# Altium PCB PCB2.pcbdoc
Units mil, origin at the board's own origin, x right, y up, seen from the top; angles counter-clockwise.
Board outline 3655 x 4282.74 mil, 2 copper layers (Top Layer, Bottom Layer); 22 components, 12 nets, 101 pads, 23 vias.
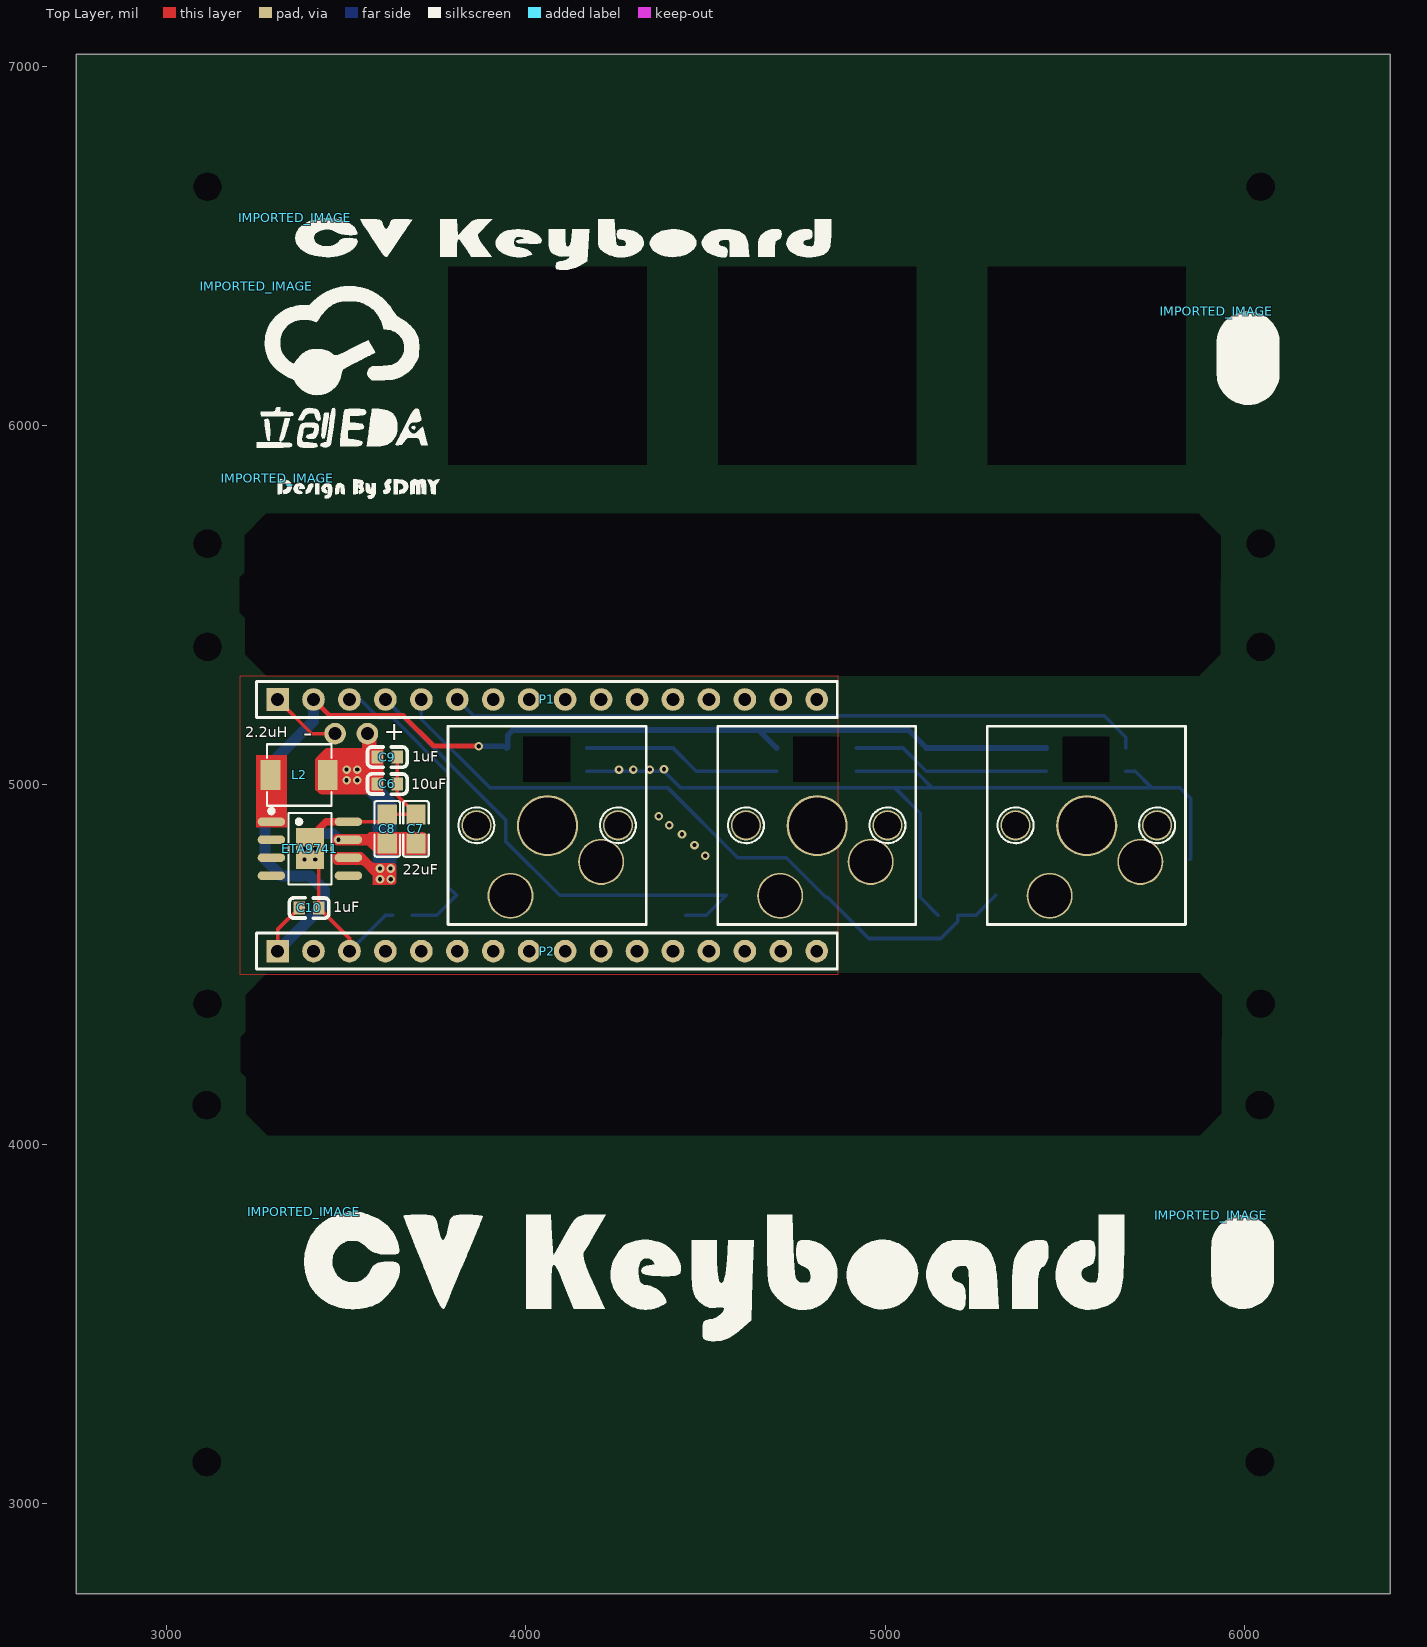
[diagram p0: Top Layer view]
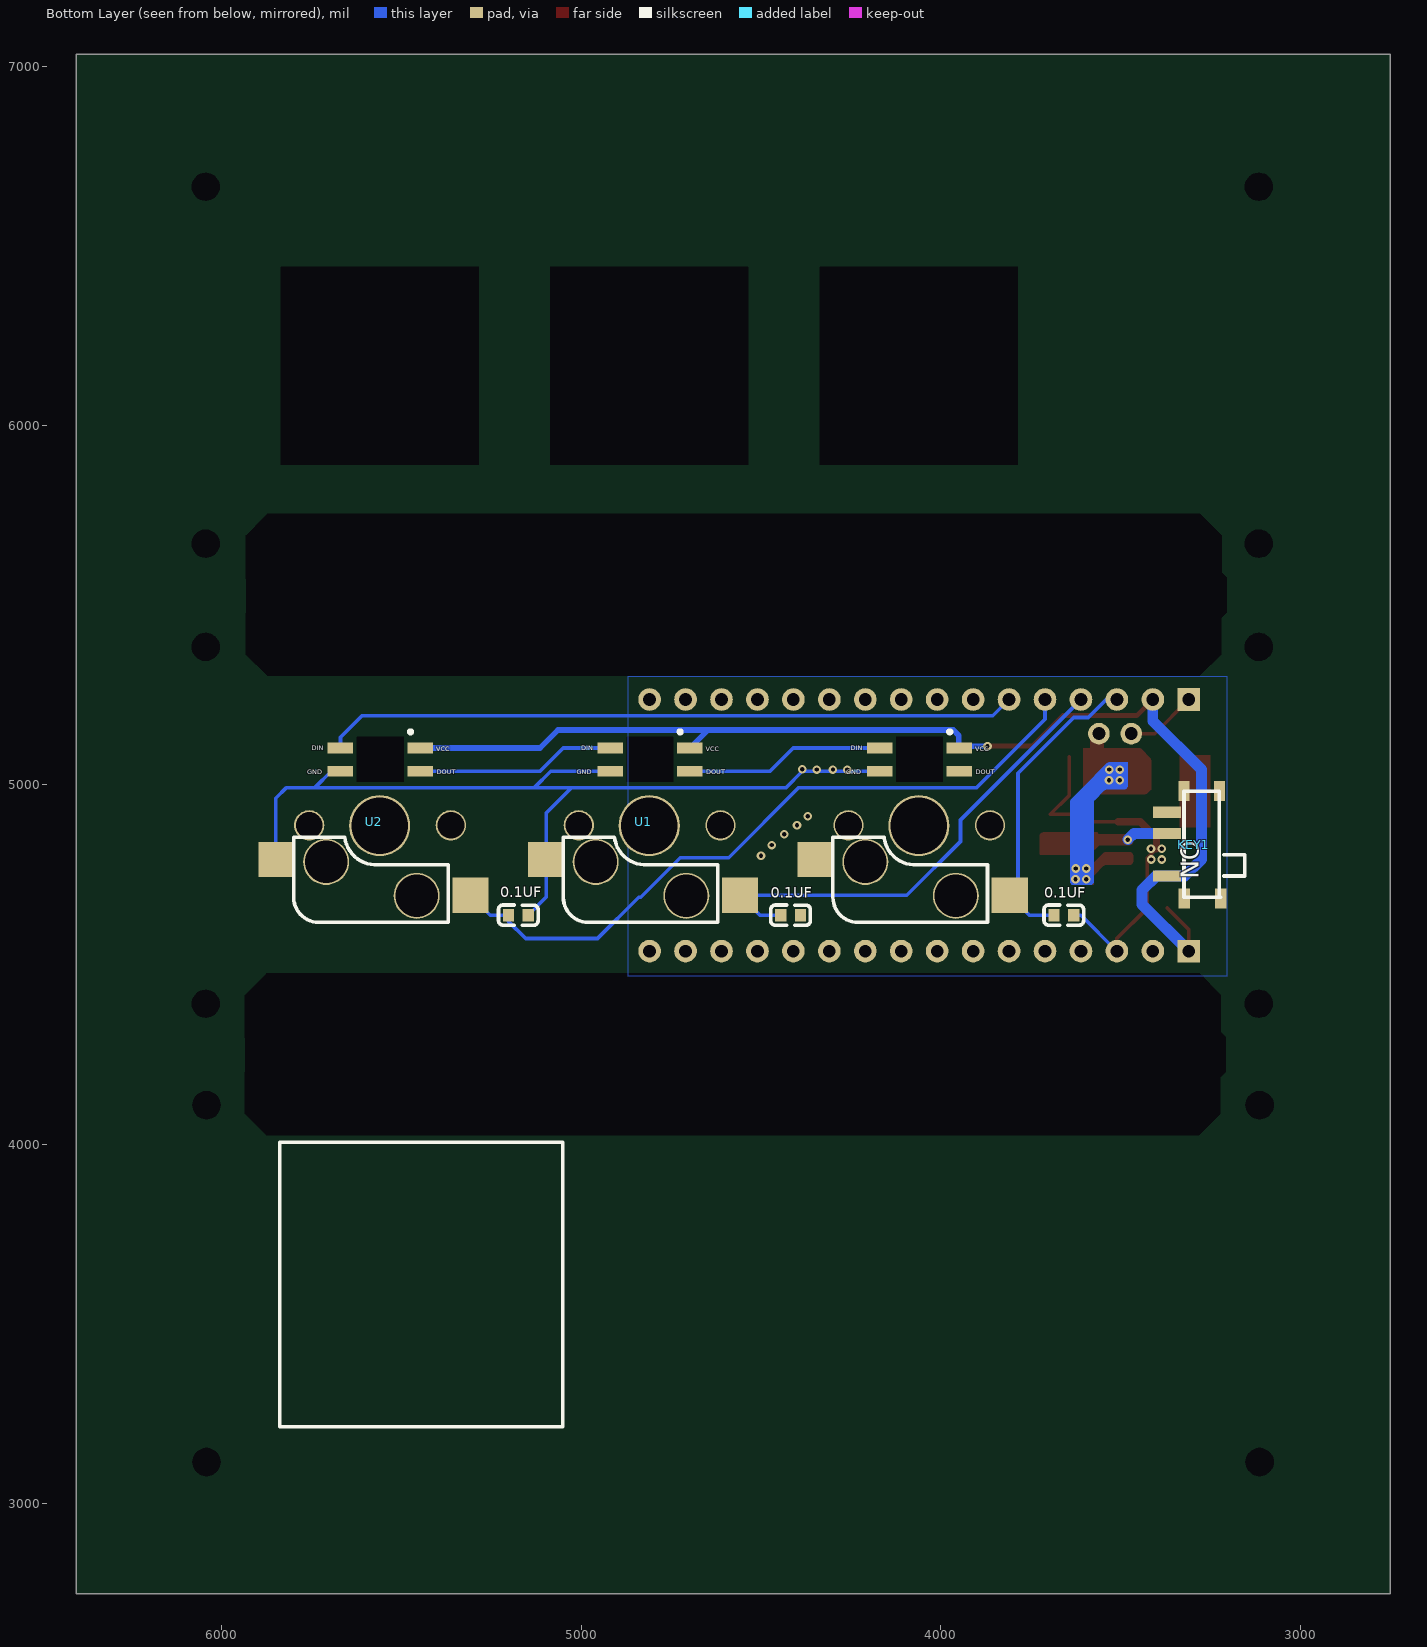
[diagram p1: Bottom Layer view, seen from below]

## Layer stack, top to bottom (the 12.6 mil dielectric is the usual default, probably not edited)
Top Solder: solder mask 0.4, Solder Resist, Dk 3.5
Top Layer: signal copper 1.4
Dielectric 1: dielectric 12.6, FR-4, Dk 4.8
Bottom Layer: signal copper 1.4
Bottom Solder: solder mask 0.4, Solder Resist, Dk 3.5

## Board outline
6405,2750 2750,2750 2750,7032.74 6405,7032.74
cut-out: 3154.49,4391.28 ccw(c3115.12,4391.28) 3075.75,4391.28 ccw(c3115.12,4391.28)
cut-out: 3154.49,5384.2 ccw(c3115.12,5384.2) 3075.75,5384.2 ccw(c3115.12,5384.2)
cut-out: 6084.37,5384.2 ccw(c6045,5384.2) 6005.63,5384.2 ccw(c6045,5384.2)
cut-out: 6084.37,4391.28 ccw(c6045,4391.28) 6005.63,4391.28 ccw(c6045,4391.28)
cut-out: 3154.49,6664.2 ccw(c3115.12,6664.2) 3075.75,6664.2 ccw(c3115.12,6664.2)
cut-out: 3154.49,5671.28 ccw(c3115.12,5671.28) 3075.75,5671.28 ccw(c3115.12,5671.28)
cut-out: 6084.37,5671.28 ccw(c6045,5671.28) 6005.63,5671.28 ccw(c6045,5671.28)
cut-out: 6084.37,6664.2 ccw(c6045,6664.2) 6005.63,6664.2 ccw(c6045,6664.2)
cut-out: 3152.29,3116.28 ccw(c3112.92,3116.28) 3073.55,3116.28 ccw(c3112.92,3116.28)
cut-out: 3152.29,4109.2 ccw(c3112.92,4109.2) 3073.55,4109.2 ccw(c3112.92,4109.2)
cut-out: 6082.17,4109.2 ccw(c6042.8,4109.2) 6003.43,4109.2 ccw(c6042.8,4109.2)
cut-out: 6082.17,3116.28 ccw(c6042.8,3116.28) 6003.43,3116.28 ccw(c6042.8,3116.28)
cut-out: 3785.4,5891.14 4336.6,5891.14 4336.6,6442.34 3785.4,6442.34
cut-out: 4535.4,5891.14 5086.6,5891.14 5086.6,6442.34 4535.4,6442.34
cut-out: 5285.4,5891.14 5836.6,5891.14 5836.6,6442.34 5285.4,6442.34
cut-out: 3207.43,4299.57 3221.24,4313.38 3221.24,4315.76 3221.24,4416.93 3280.07,4475.76 3281.24,4475.76 3281.28,4475.72 3304.71,4475.72 5876.28,4475.72 5881.24,4470.76 5935.07,4416.93 5936.24,4416.93 5936.24,4315.76 5935,4272.74 5935,4217.74 5935.64,4185.76 5935.64,4084.6 5876.81,4025.76 5876.24,4025.76 3281.24,4025.76 3222.43,4084.57 3222.43,4185.73 3207.43,4200.73
cut-out: 3205,5577.74 3218.81,5591.55 3218.81,5593.93 3218.81,5695.1 3277.64,5753.93 3278.81,5753.93 3278.85,5753.89 3302.27,5753.89 5873.85,5753.89 5878.81,5748.93 5932.64,5695.1 5933.81,5695.1 5933.81,5593.93 5932.57,5550.91 5932.57,5495.91 5933.21,5463.93 5933.21,5362.77 5874.38,5303.93 5873.81,5303.93 3278.81,5303.93 3220,5362.74 3220,5463.91 3205,5478.91

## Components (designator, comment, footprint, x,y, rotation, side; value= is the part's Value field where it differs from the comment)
0.1UF "0603 100nf" C0603 4417.56,4637.74 r180 bottom
0.1UF "0603 100nf" C0603 3657.44,4637.74 r180 bottom
0.1UF "0603 100nf" C0603 5175,4637.74 r180 bottom
C6 "0603" C0603 3615,5002.74 r180 top
C7 "0805" C0805 3695,4877.74 r90 top
C8 "0805" C0805 3615,4877.74 r90 top
C9 "0603" C0603 3615,5077.74 r180 top
C10 "0603 1uf" C0603_3 3397.44,4657.74 r180 top
ETA9741 "ETA9741" SOIC-8_L4.9-W3.9-P1.27-LS6.0-BL-EP2.9 3400,4822.74 r270 top
IMPORTED_IMAGE "IMPORTED_IMAGE" IMPORTED_IMAGE 3384.41,3812.74 r0 top
IMPORTED_IMAGE "IMPORTED_IMAGE" IMPORTED_IMAGE 3359.63,6577.74 r0 top
IMPORTED_IMAGE "IMPORTED_IMAGE" IMPORTED_IMAGE 5923,6317.74 r0 top
IMPORTED_IMAGE "IMPORTED_IMAGE" IMPORTED_IMAGE 5908,3802.74 r0 top
IMPORTED_IMAGE "IMPORTED_IMAGE" IMPORTED_IMAGE 3310,5852.74 r0 top
IMPORTED_IMAGE "IMPORTED_IMAGE" IMPORTED_IMAGE 3252.5,6387.74 r0 top
KEY1 "MSK-12C02" MSK-11027 3410,4687.74 r90 bottom
L2 "0420CDMCCDS-2R2MC" IND-SMD_L4.4-W4.2 3370,5027.74 r180 top
P1 "2.54-1*16P母" HDR-TH_16P-P2.54-V-F-1 4060,5237.74 r0 top
P2 "2.54-1*16P母" HDR-TH_16P-P2.54-V-F-1 4060,4537.74 r0 top
U1 "KAILH_WS2182B_3528反贴_无二极管" KAILH_WS2182B_3528反贴_无二极管_封装 4810,4887.74 r0 top
U2 "KAILH_WS2182B_3528反贴_无二极管" KAILH_WS2182B_3528反贴_无二极管_封装 5560,4887.74 r0 top
? "KAILH_WS2182B_3528反贴_无二极管" KAILH_WS2182B_3528反贴_无二极管_封装 4060,4887.74 r0 top

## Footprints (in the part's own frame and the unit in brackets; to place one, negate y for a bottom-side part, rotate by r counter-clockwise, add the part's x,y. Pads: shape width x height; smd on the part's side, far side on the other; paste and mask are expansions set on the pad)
C0603 [mm]
  rect 0.8x0.9 smd: 1(-0.7,0) 2(0.7,0)
  silkscreen extent -1.41,-0.71 1.39,0.72
C0603_3 [mm]
  rect 0.8x0.9 smd: 1(-0.7,0) 2(0.7,0)
  silkscreen extent -1.41,-0.71 1.39,0.72
C0805 [mm]
  rect 1.41x1.35 smd: 1(-1.03,0) 2(1.03,0)
  silkscreen extent -1.96,-0.9 1.96,0.9
HDR-TH_16P-P2.54-V-F-1 [mil]
  rect 63x63 hole 35.4: 1(-750,0)
  round 63 hole 35.4: 2(-650,0) 3(-550,0) 4(-450,0) 5(-350,0) 6(-250,0) 7(-150,0) 8(-50,0) 9(50,0) 10(150,0) 11(250,0) 12(350,0) 13(450,0) 14(550,0) 15(650,0) 16(750,0)
  silkscreen extent -809,-50 807,50
IMPORTED_IMAGE [mil]
  silkscreen extent 0,-360 2281,0
IND-SMD_L4.4-W4.2 [mil]
  rect 55.1x83.5 smd: 1(79.8,0) 2(-79.8,0)
  silkscreen extent -90,-86 90,86
KAILH_WS2182B_3528反贴_无二极管_封装 [mil]
  rect 100.39x98.42 smd far side: 5(288,-95) 6(-252,-195)
  round 128 hole 118.11: 7(150,-102) 8(-102,-196)
  round 170 hole 157.48: 9(1,-1)
  round 84 hole 74.8 unplated: 10(-197,0) 11(197,0)
  rect 70.87x29.53 smd far side: DIN(110,215) DOUT(-112,150) GND(110,150) VCC(-112,215)
  Multi-Layer board cut-out: -66,246 -66,121.59 64.16,121.59 64.16,246
  silkscreen extent -276,-276 276,276
MSK-11027 [mm]
  rect 0.8x2 smd: 1(1.5,-1) 2(4.5,-1) 3(6,-1)
  rect 1.4x0.8 smd: 4(-0.084,-2.21) 5(7.5,-2.201) 6(7.512,-4.71) 7(-0.093,-4.796)
  silkscreen extent 0,-6.5 7.5,-2.2
SOIC-8_L4.9-W3.9-P1.27-LS6.0-BL-EP2.9 [mil]
  oval 23.7x76.4 smd: 1(-75,-107.1) 2(-25,-107.1) 3(25,-107.1) 4(75,-107.1) 5(75,107.1) 6(25,107.1) 7(-25,107.1) 8(-75,107.1)
  rect 114.2x78.7 smd: 9(0,0)
  silkscreen extent -111,-113 100,60

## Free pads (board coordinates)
  round 60 hole 36: 1(3560,5142.74) 2(3470,5142.74)

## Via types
v1: diameter 24.02, hole 12.01, Top Layer to Bottom Layer, 23 vias

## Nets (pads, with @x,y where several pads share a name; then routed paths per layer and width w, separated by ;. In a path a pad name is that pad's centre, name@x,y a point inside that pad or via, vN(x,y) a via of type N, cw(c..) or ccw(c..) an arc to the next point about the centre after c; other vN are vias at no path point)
$1N361: ETA9741.1 L2.1
$1N4537: U1.DIN U2.DOUT | length 554.9
  Bottom Layer w10: U1.DIN 5050,5102.74 5115,5037.74 U2.DOUT
$1N4553: ?.DIN U1.DOUT | length 554.9
  Bottom Layer w10: ?.DIN 4410,5102.74 4475,5037.74 U1.DOUT
+5V: C7.1 C8.1 ETA9741.7 KEY1.2 | length 85.9
  Bottom Layer w30: KEY1.2@3400.63,4864.91 3462.56,4864.91 v1(3479.48,4847.99)
BAT: C6.2 C9.2 ETA9741.6 L2.2 pad.1 | length 82.1
  Top Layer w39.37: pad.1@3560,5147.74 3565,5142.74 3565,5067.74
  other v1: 3595,4737.74 3625,4737.74 3595,4767.74 3624.38,4767.74 3502,5012.74 3532,5012.74 3502,5042.74 3531.38,5042.74
GND: 0.1UF.2 ?.5 ?.GND C6.1 C7.2 C8.2 C9.1 C10.1 ETA9741.8 ETA9741.9 P1.1 P1.8 P1.16 P2.3 P2.16 pad.2 U1.5 U1.GND U2.5 U2.GND | length 3834.9
  Top Layer w10: P1.1 3405,5142.74 pad.2@3475,5142.74 ; ETA9741.9 3425,4797.74 C10.1 3510,4572.74 P2.3 ; ETA9741.8 3594.45,4897.74 C8.2 C7.2 3642.56,4970.73 C6.1 C9.1
  Top Layer w20: ETA9741.9 3400,4852.74 3445,4897.74 ETA9741.8
  Bottom Layer w10: P2.3 3610,4637.74 0.1UF.2@3629.88,4637.74 ; ?.GND 4260,5037.74 4385,5037.74 4430,4992.74 5026.33,4992.74 ; U1.GND 5085,5037.74 5130,4992.74 ; 0.1UF.2@5147.44,4637.74 5098,4687.18 U1.5 5098,4921.07 5026.33,4992.74 ; U2.GND 5696.04,5037.74 5741.04,4992.74 ; U2.5 5850,4794.74 5850,4962.74 5820,4992.74 5741.04,4992.74 ; 5026.33,4992.74 5130,4992.74 ; 5130,4992.74 5741.04,4992.74
  other v1: 3385,4792.74 3414.38,4792.74 4500,4802.74 3385,4822.74 3415,4822.74 4470,4832.74 4435,4862.74 4400,4887.74 4370,4912.74 4260,5042.74 4300,5042.74 4345,5042.74 4385,5043.55
IO4: 0.1UF.1@5202.56,4637.74 P1.5 U2.6 | length 1965.6
  Bottom Layer w10: P1.5 3710,5182.74 3900,4992.74 4395,4992.74 4590,4797.74 4725,4797.74 4835,4687.74 4840,4687.74 4955,4572.74 5155,4572.74 5202.56,4620.3 5202.56,4637.74 5253,4637.74 U2.6
IO5: P1.6 U2.DIN | length 1933.5
  Bottom Layer w10: P1.6 3855,5192.74 5610,5192.74 5670,5132.74 U2.DIN
IO8: 0.1UF.1@4445.12,4637.74 P1.4 U1.6 | length 1344.6
  Bottom Layer w10: P1.4 3945,4902.74 3945,4842.74 4095,4692.74 U1.6 4503,4637.74 0.1UF.1@4445.12,4637.74
IO9: 0.1UF.1@3685,4637.74 ?.6 P1.3 | length 855.2
  Bottom Layer w10: P1.3 3540,5237.74 3590,5187.74 3630,5187.74 3785,5032.74 3785,4715.74 ?.6 3753,4637.74 0.1UF.1@3685,4637.74
VCC: ?.VCC C10.2 KEY1.1 P1.2 P2.1 U1.VCC U2.VCC | length 3295
  Top Layer w10: P2.1 3310,4597.86 C10.2
  Top Layer w13.78: P1.2 3455,5192.74 3660,5192.74 3745,5107.74 v1(3870,5107.74)
  Bottom Layer w15.75: v1(3870,5107.74) 3943,5107.74 ?.VCC 3950,5104.74 3950,5137.74 3965,5152.74 4648,5152.74 ; U1.VCC 4648,5152.74 ; U2.VCC 5115,5102.74 5065,5152.74 4648,5152.74
  Bottom Layer w30: KEY1.1@3400.63,4746.8 3320.94,4746.8 3275,4792.74 3275,5042.74 3410,5177.74 P1.2
  Bottom Layer w31.5: P2.1 3440,4667.74 3440,4707.43 KEY1.1@3400.63,4746.8
"": 
pads on no net: ?.7 ?.8 ?.9 ?.10 ?.11 ?.DOUT ETA9741.2 ETA9741.3 ETA9741.4 ETA9741.5 KEY1.3 KEY1.4 KEY1.5 KEY1.6 KEY1.7 P1.7 P1.9 P1.10 P1.11 P1.12 P1.13 P1.14 P1.15 P2.2 P2.4 P2.5 P2.6 P2.7 P2.8 P2.9 P2.10 P2.11 P2.12 P2.13 P2.14 P2.15 U1.7 U1.8 U1.9 U1.10 U1.11 U2.7 U2.8 U2.9 U2.10 U2.11

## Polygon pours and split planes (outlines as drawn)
GND on Top Layer (solid, remove dead copper): 3205,4472.74 4870,4472.74 4870,5302.74 3205,5302.74
GND on Bottom Layer (solid, remove dead copper, pour order 1): 3205,4467.74 4870,4467.74 4870,5302.74 3205,5302.74

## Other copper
Top Layer:
  region net $1N361: 3250,4882.74 3335,4882.74 3335,5082.74 3250,5082.74
  region net +5V: 3475,4832.74 3554.98,4832.74 cw(c3554.98,4822.74) 3562.05,4829.81 3582.5,4809.36 ccw(c3589.57,4816.43) 3589.57,4806.43 3723.69,4806.43 3725,4807.74 3725,4857.74 ccw(c3715,4857.74) 3715,4867.74 3565,4867.74 3560,4862.74 3475,4862.74 ccw(c3475,4852.74) 3465,4852.74 3465,4842.74 ccw(c3475,4842.74)
  region net BAT: 3475,4812.74 3540.86,4812.74 cw(c3540.86,4802.74) 3547.93,4809.81 3572.07,4785.67 ccw(c3579.14,4792.74) 3579.14,4782.74 3630,4782.74 cw(c3630,4772.74) 3640,4772.74 3640,4732.74 cw(c3630,4732.74) 3630,4722.74 3580,4722.74 3575,4722.74 3575,4743.6 ccw(c3565,4743.6) 3572.07,4750.67 3547.93,4774.81 ccw(c3540.86,4767.74) 3540.86,4777.74 3475,4777.74 cw(c3475,4787.74) 3465,4787.74 3465,4802.74 cw(c3475,4802.74)
  region net BAT: 3417.93,5075.67 3441.45,5099.19 cw(c3448.52,5092.12) 3448.52,5102.12 3603.97,5102.12 3603.97,4984.8 cw(c3593.97,4984.8) 3593.97,4974.8 3431.62,4974.8 cw(c3431.62,4984.8) 3424.55,4977.73 3415.28,4987 3415,4987.28 3415,5068.6 cw(c3425,5068.6)
Bottom Layer:
  region net BAT: 3490,4987.74 3537.96,4987.74 cw(c3537.96,4977.74) 3545.03,4984.81 3571.87,4957.98 cw(c3564.8,4950.91) 3574.8,4950.91 3574.8,4727.94 3580,4722.74 3635,4722.74 3640,4727.74 3640,4953.6 ccw(c3630,4953.6) 3637.07,4960.67 3605,4992.74 3537.93,5059.81 ccw(c3530.86,5052.74) 3530.86,5062.74 3485,5062.74 3480,5062.74 3480,4997.74 ccw(c3490,4997.74)

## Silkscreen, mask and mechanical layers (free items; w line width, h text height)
Top Overlay:
  text "2.2uH" at 3219.94,5132.73 h29.2
  text "+" at 3605,5125.03 h51.47
  text "-" at 3381.1,5120.66 h51.47
  text "1uF" at 3685.01,5065.23 h29.2
  text "10uF" at 3681.22,4987.73 h29.2
  text "22uF" at 3658.77,4750.23 h29.2
  text "1uF" at 3465.06,4645.23 h29.2
Bottom Overlay:
  lines w10: 5051.3,3214.04 5838.7,3214.04 5838.7,4006.44 5051.3,4006.44 5051.3,3214.04
  text "ON" at 3332.48,4844.86 h51.1 r90
Mechanical 1:
  drawing of 160 lines, arcs and shapes, not listed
